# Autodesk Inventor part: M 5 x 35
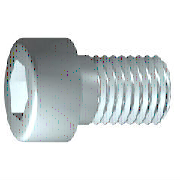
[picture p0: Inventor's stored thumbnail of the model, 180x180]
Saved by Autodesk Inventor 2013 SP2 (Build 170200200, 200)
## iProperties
IsCustomPart: 0
Company: 한국ATC센터
Created: 2014-12
Part Number: M 5 x 35
Material: 강, 연강
Description: 6각머리 태핑 나사
Document SubType Name: Modeling
Standard: KS B 1003
Designer: KYOUNG IL JANG
Standards Organization: KS
Language: ko-KR
Size Designation: M 5 x 35
Categories: <MemberInstance><Categories><Category DisplayName="조임쇠" InternalName="e4da775c-781d-43d5-af7c-5136215cf5a6" Mnemonic="FSTN"><Category DisplayName="볼트" InternalN
Density: 7.86 g/cm^3
Mass: 7.27786 g
Surface Area: 8.23857 cm^2
Volume: 0.925936 cm^3
Author: KYOUNG IL JANG
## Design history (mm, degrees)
sketch "스케치1"
  geometry: L1 (-1.167, 0)-(35, 0); L2 (35, 0)-(35, 2.5); L3 (35, 2.5)-(13, 2.5); L4 (13, 2.5)-(12.509, 2.5); L5 (12.509, 2.5)-(0, 2.5); L6 (0, 2.5)-(0, 4.25); L7 (0, 4.25)-(-5, 4.25); L8 (-5, 4.25)-(-5, 2.309); L9 (-5, 2.309)-(-2.5, 2.309); L10 (-2.5, 2.309)-(-1.167, 0); L11 (-13, 0)-(43, 0) reference; L12 (0, -0.85)-(0, 5.1) reference; L13 (13, 2.5)-(0, 2.5)
  constraints: 22 end point, 6 parallel, 2 collinear, 2 perpendicular, 1 horizontal, 1 point on line
  dimensions: "d1" = 22 distance from line of L3.end L2 (= GEL); "d2" = 0.49086 distance of L4.end L3.end (computed from GAL); "d3" = 5 distance between parallel lines of L8 L6 (= KOH); "d4" = 2.5 distance of L8.end L9.end (= INTI); "d5" = 60 deg angle of L10 L1; "d6" = 5 diameter of L3 L1 (= GD); "d7" = 5 diameter of L5 L1 (= BDM); "d8" = 4.6188 diameter of L9 L1 (= 1.1547 x SW); "d9" = 8.5 diameter of L7 L1 (= KOD); "d26" = 35 distance between parallel lines of L12 L2 (= NLG)
revolve "본체" sketch "스케치1" stored, may be unused: angle "d10" = 90 deg
sketch "스케치2"
  geometry: L1 (0, -5.95)-(0, 5.95) reference; L2 (-5.95, 0)-(5.95, 0) reference; L3 (2.309, 0)-(1.155, -2); L4 (1.155, -2)-(-1.155, -2); L5 (-1.155, -2)-(-2.309, 0); L6 (-2.309, 0)-(-1.155, 2); L7 (-1.155, 2)-(1.155, 2); L8 (1.155, 2)-(2.309, 0); 2 further points
  constraints: 12 end point, 1 coincident, 1 horizontal alignment, 1 point on line, 12 other
extrude "슬롯" join sketch "스케치2" stored distance "d11" = 10; taper "d12" = 0 deg
workplane "Work Plane1"
fillet "Fillet2" dims "d30" = 0.1 (= R)
body "Solid1"
fillet "모깎기1" dims "d17" = 0.5 (= RR)
feature "스레드" dims "d13" = 22 (= GEL), "d14" = 0
chamfer "모따기1" distance "d15" = 0.49076 (= -0.5 x SPD + 0.5 x GD); stored, may be unused: second distance "d16" = 0.49076 (= GUL), angle "d27" = 45 deg
other parameters: "GD" = 5 (= NND) [user parameter; used in 2 equation terms], "NLG" = 35 [user parameter; used in 1 equation term], "GEL" = 22 [user parameter; used in 2 equation terms], "KOD" = 8.5 [user parameter; used in 1 equation term], "KOH" = 5 [user parameter; used in 1 equation term], "INTI" = 2.5 [user parameter; used in 1 equation term], "GAL" = 0.49076 (= 0.61345 x PTC) [user parameter; used in 1 equation term], "GUL" = 0.49076 (= 0.61345 x PTC) [user parameter; used in 1 equation term], "BDM" = 5 (= NND) [user parameter; used in 1 equation term], "SW" = 4 [user parameter; used in 2 equation terms], "RR" = 0.5 [user parameter; used in 1 equation term], "SPD" = 4.01848 (= NND - 1.2269 x PTC) [user parameter; used in 1 equation term], "d19" = 0, "d28" = 0, "d29" = 0, "R" = 0.1 [user parameter; used in 1 equation term], "PHH" = 0.2 [user parameter], "GD1" = 4.01848 (= THREADDIA - 1.2269 x PTC) [user parameter], "THREADDIA" = 5 [user parameter; used in 1 equation term], "FAWI" = 45 deg [user parameter], "TPU" = 12.5 (computed from PTC) [user parameter], "PTC" = 0.8 [user parameter; used in 5 equation terms], "NND" = 5 [user parameter; used in 3 equation terms], "TOA" = 30 deg [user parameter], "E0" = 4.62 (= 1.155 x SW) [user parameter]
